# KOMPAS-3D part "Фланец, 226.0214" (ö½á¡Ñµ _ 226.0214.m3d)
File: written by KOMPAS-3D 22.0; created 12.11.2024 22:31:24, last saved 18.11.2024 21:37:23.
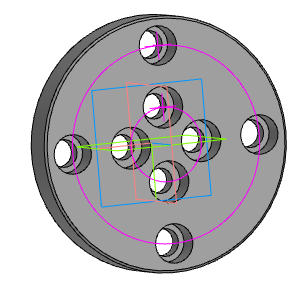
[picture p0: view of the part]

Document properties: Автор: aleksander.larionov.10@gmail.com; Полное имя файла: C:\Мои папки\Работа\Крышки, фланцы\226.0214\Фланец _ 226.0214.m3d

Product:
- Part/product: Фланец  | designation 226.0214
    Материал: Сталь 45 ГОСТ 1050-2013 (density 7810 kg/m3)
    Масса: 1.122335

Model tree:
1. Эскиз:1
2. Элемент выдавливания:1
     Расстояние 1 = 18
3. Эскиз:2  (with: Элемент выдавливания:1)
4. Отверстие:1  (with: Элемент выдавливания:1)
     Глубина выреза = 18; Диаметр отверстия = 12; Угол конуса дна = 118; Расстояние 1 = 42.5; Диаметр цековки = 17; Глубина цековки = 11
5. Отверстие:2  (with: Элемент выдавливания:1)
     Глубина выреза = 18; Диаметр отверстия = 11; Угол конуса дна = 118; Расстояние 1 = 16; Диаметр цековки = 18; Глубина цековки = 11
6. Массив по концентрической сетке:1  (with: Отверстие:1, Отверстие:2)  (4 pattern instances)
     Шаг 2 = 360
7. Фаска:1  (with: Элемент выдавливания:1)  (labels: Сталь 45 ГОСТ 1050-2013)
     Угол = 45; Длина 1 = 1; Длина 2 = 1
